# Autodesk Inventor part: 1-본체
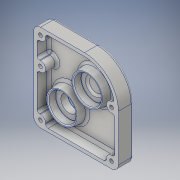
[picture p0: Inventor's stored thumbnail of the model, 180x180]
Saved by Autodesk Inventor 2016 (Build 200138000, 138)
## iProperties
Created: 2015-11
Part Number: 1-본체
Material: Aluminum 6061
Document SubType Name: Modeling
Designer: Administrator
Density: 2.7 g/cm^3
Appearance: Aluminum - Flat
Mass: 246.699 g
Surface Area: 389.358 cm^2
Volume: 91.3698 cm^3
Author: Administrator
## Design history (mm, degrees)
sketch "Sketch1"
  geometry: L1 (-30, 73)-(70, 73); L2 (70, 73)-(70, -30); L3 (70, -30)-(-30, -30); L4 (-30, -30)-(-30, 73); 1 further point
  constraints: 8 end point, 2 parallel, 1 horizontal, 1 perpendicular
  dimensions: "d0" = 100 distance of L2.end L3.end; "d1" = 103 distance of L3.end L1.start; "d2" = 30 distance from line of point (0, 0) L4; "d3" = 30 distance from line of point (0, 0) L3
extrude "Extrusion1" new body sketch "Sketch1" distance "d4" = 18; taper "d5" = 0 deg
fillet "Fillet1" dims "d6" = 40
shell "Shell1" dims "d7" = 4
sketch "Sketch2"
  geometry: L1 (-30, -30)-(70, -30) reference; L2 (-30, 73)-(-30, -30) reference; L3 (-22, 59)-(-26, 59); L4 (-26, -26)-(-26, 69) reference; L5 (-16, 65)-(-16, 69); L6 (-22, 39)-(-26, 39); L7 (-22, 27)-(-26, 27); L8 (-22, -16)-(-26, -16); L9 (-16, -22)-(-16, -26); L10 (66, -26)-(-26, -26) reference; L11 (62, 27)-(66, 27); L12 (62, 39)-(65.496, 39); L13 (56, -22)-(56, -26); L14 (62, -16)-(66, -16); L15 (66, 33)-(66, -26) reference; L16 (-26, 69)-(30, 69) reference; L17 (-26, 59)-(-26, 69); L18 (-16, 69)-(-26, 69); L19 (-26, 39)-(-26, 27); L20 (-26, -16)-(-26, -26); L21 (-16, -26)-(-26, -26); L22 (66, 33)-(66, -26) reference; L23 (66, 27)-(66, 33); L24 (66, -16)-(66, -26); L25 (66, -26)-(56, -26); A1 r 6 centre (-22, 65) between (-22, 59) and (-16, 65); A2 r 6 centre (-22, 33) between (-22, 27) and (-22, 39); A3 r 6 centre (-22, -22) between (-16, -22) and (-22, -16); A4 r 6 centre (62, 33) between (62, 39) and (62, 27); A5 r 6 centre (62, -22) between (62, -16) and (56, -22); A6 r 36 centre (30, 33) between (66, 33) and (30, 69) reference; A7 r 36 centre (30, 33) between (66, 33) and (65.496, 39); 1 further point
  constraints: 36 end point, 13 point on circle, 10 tangent, 8 collinear, 8 perpendicular, 7 point on line, 6 centre point, 5 equal radius, 3 vertical alignment, 2 horizontal, 2 horizontal alignment
  dimensions: "d9" = 12 diameter of A1; "d10" = 84 horizontal distance of A4.centre A1.centre; "d11" = 32 vertical distance of A4.centre A1.centre; "d12" = 55 distance of A5.centre A4.centre; "d13" = 8 distance from line of A5.centre L1; "d14" = 8 distance from line of L2 A1.centre
extrude "Extrusion2" join sketch "Sketch2" stored distance "d15" = 18; taper "d16" = 0 deg
fillet "Fillet2" dims "d17" = 8
sketch "Sketch4"
  geometry: A1 r 6 centre (-62, 33) between (-62, 27) and (-62, 39) reference; A2 r 6 centre (-62, -22) between (-56, -22) and (-62, -16) reference; A3 r 6 centre (22, 65) between (16, 65) and (22, 59) reference; A4 r 6 centre (22, 33) between (22, 39) and (22, 27) reference; A5 r 6 centre (22, -22) between (22, -16) and (16, -22) reference; 1 further point
hole "Hole1" sketch "Sketch4" at (-62, -22), (22, -22), (22, 33), (22, 65), (-62, 33) diameter "d18" = 4.5; stored, may be unused: countersink angle "d22" = 90 deg, drill point angle "d24" = 118 deg; dims "d19" = 6, "d20" = 8, "d21" = 4.4, "d23" = 8
sketch "Sketch6"
  geometry: C1 r 20 at (46, 59); C2 r 20 at (16, 26); A1 r 40 centre (46, 59) between (86, 59) and (46, 99) reference; 1 further point
  constraints: 2 centre point, 1 coincident, 1 concentric, 1 equal radius
  dimensions: "d27" = 40 diameter of C1
extrude "Extrusion3" join sketch "Sketch6" distance "d29" = 11; taper "d30" = -10 deg
hole "Hole2" diameter "d33" = 22; stored, may be unused: countersink angle "d37" = 90 deg, drill point angle "d39" = 0 deg; dims "d31" = 10, "d32" = 10, "d34" = 6, "d35" = 32, "d36" = 9, "d38" = 11
sketch "Sketch7"
  geometry: C1 r 25 at (0, 0); 1 further point
  constraints: 1 centre point, 1 coincident
  dimensions: "d40" = 50 diameter of C1
extrude "Extrusion4" join sketch "Sketch7" distance "d41" = 15; taper "d42" = -10 deg
hole "Hole3" diameter "d45" = 20; stored, may be unused: countersink angle "d49" = 90 deg, drill point angle "d51" = 0 deg; dims "d43" = 10, "d44" = 10, "d46" = 6, "d47" = 32, "d48" = 9, "d50" = 11
hole "Hole4" diameter "d54" = 24; stored, may be unused: countersink angle "d58" = 90 deg, drill point angle "d60" = 0 deg; dims "d52" = 10, "d53" = 10, "d55" = 6, "d56" = 28, "d57" = 11, "d59" = 13
sketch "Sketch8"
  geometry: L1 (-34.887, 56.602)-(14.887, 56.602); L2 (14.887, 56.602)-(14.887, 49.398); L3 (14.887, 49.398)-(-34.887, 49.398); L4 (-34.887, 49.398)-(-34.887, 56.602); L5 (30, -22)-(30, 65) reference; L6 (22, 73)-(-30, 73) reference; 4 further points
  constraints: 2 midpoint, 1 horizontal alignment, 1 vertical alignment, 2 other
  dimensions: "d61" = 40 distance from line of point (-10, 53) L5; "d62" = 20 distance from line of point (-10, 53) L6
emboss "Emboss1" sketch "Sketch8" dims "d0" = 100, "d1" = 103, "d2" = 30, "d3" = 30, "d63" = 0.5, "d64" = 0
sketch "Sketch9"
  geometry: 2 further points
  constraints: 1 vertical alignment
  dimensions: "d65" = 18 distance of point (0, 0) point (0, 18)
hole "Hole5" sketch "Sketch9" at (0, 18) diameter "d66" = 2.459; stored, may be unused: countersink angle "d70" = 90 deg, drill point angle "d72" = 118 deg; dims "d67" = 8, "d68" = 28, "d69" = 11, "d71" = 10
pattern_circular "Circular Pattern1" dims angle "d74" = 360 deg
fillet "Fillet3" dims "d76" = 0.3
chamfer "Chamfer1" distance "d77" = 1; stored, may be unused: second distance "d78" = 2, angle "d79" = 45 deg
fillet "Fillet4" dims "d80" = 3
fillet "Fillet5" dims "d81" = 3
fillet "Fillet6" dims "d82" = 3
fillet "Fillet7" dims "d83" = 3
body "Solid1"
